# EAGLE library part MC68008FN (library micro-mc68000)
68xxx PROCESSOR
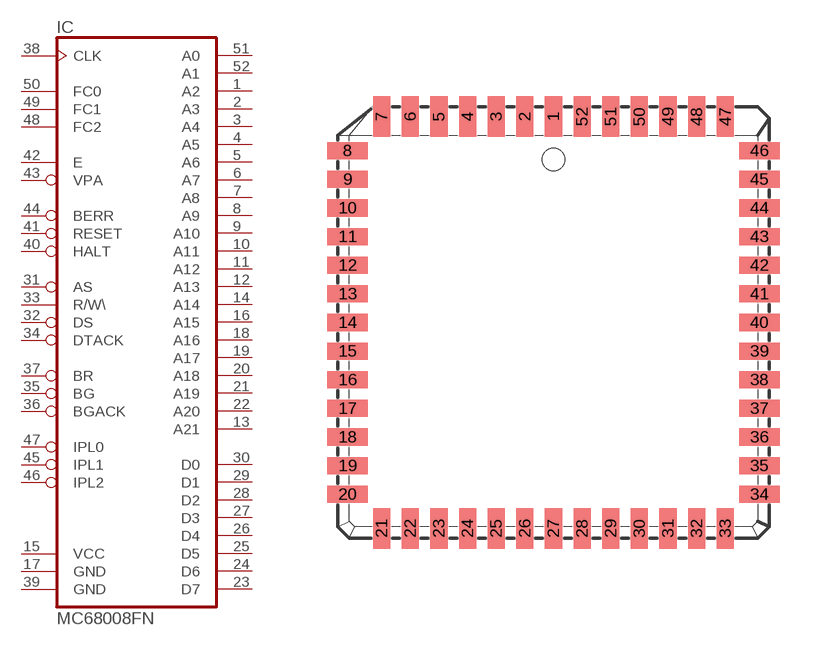
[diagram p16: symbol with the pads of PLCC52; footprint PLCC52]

Designator prefix IC

## MC68008FN  [PLCC52]
1  A2  out
2  A3  out
3  A4  out
4  A5  out
5  A6  out
6  A7  out
7  A8  out
8  A9  out
9  A10  out
10  A11  out
11  A12  out
12  A13  out
13  A21  out
14  A14  out
15  VCC  pwr
16  A15  out
17  GND  pwr
18  A16  out
19  A17  out
20  A18  out
21  A19  out
22  A20  out
23  D7
24  D6
25  D5
26  D4
27  D3
28  D2
29  D1
30  D0
31  AS  out
32  DS  out
33  R/W\  out
34  DTACK  in
35  BG  out
36  BGACK  in
37  BR  in
38  CLK  in
39  GND  pwr
40  HALT
41  RESET
42  E  out
43  VPA  in
44  BERR  in
45  IPL1  in
46  IPL2  in
47  IPL0  in
48  FC2  out
49  FC1  out
50  FC0  out
51  A0  out
52  A1  out

## Footprint PLCC52 (pad centres in mm)
PLASTIC LEADED CHIP CARRIER square
smd 0.76 x 1.8: 1 0,9.13; 2 -1.27,9.13; 3 -2.54,9.13; 4 -3.81,9.13; 5 -5.08,9.13; 6 -6.35,9.13; 7 -7.62,9.13; 21 -7.62,-9.13; 22 -6.35,-9.13; 23 -5.08,-9.13; 24 -3.81,-9.13; 25 -2.54,-9.13; 26 -1.27,-9.13; 27 0,-9.13; 28 1.27,-9.13; 29 2.54,-9.13; 30 3.81,-9.13; 31 5.08,-9.13; 32 6.35,-9.13; 33 7.62,-9.13; 47 7.62,9.13; 48 6.35,9.13; 49 5.08,9.13; 50 3.81,9.13; 51 2.54,9.13; 52 1.27,9.13
smd 1.8 x 0.76: 8 -9.13,7.62; 9 -9.13,6.35; 10 -9.13,5.08; 11 -9.13,3.81; 12 -9.13,2.54; 13 -9.13,1.27; 14 -9.13,0; 15 -9.13,-1.27; 16 -9.13,-2.54; 17 -9.13,-3.81; 18 -9.13,-5.08; 19 -9.13,-6.35; 20 -9.13,-7.62; 34 9.13,-7.62; 35 9.13,-6.35; 36 9.13,-5.08; 37 9.13,-3.81; 38 9.13,-2.54; 39 9.13,-1.27; 40 9.13,0; 41 9.13,1.27; 42 9.13,2.54; 43 9.13,3.81; 44 9.13,5.08; 45 9.13,6.35; 46 9.13,7.62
